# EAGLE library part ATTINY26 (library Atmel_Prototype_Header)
8-bit AVR Microcontroller with 2K Bytes Flash
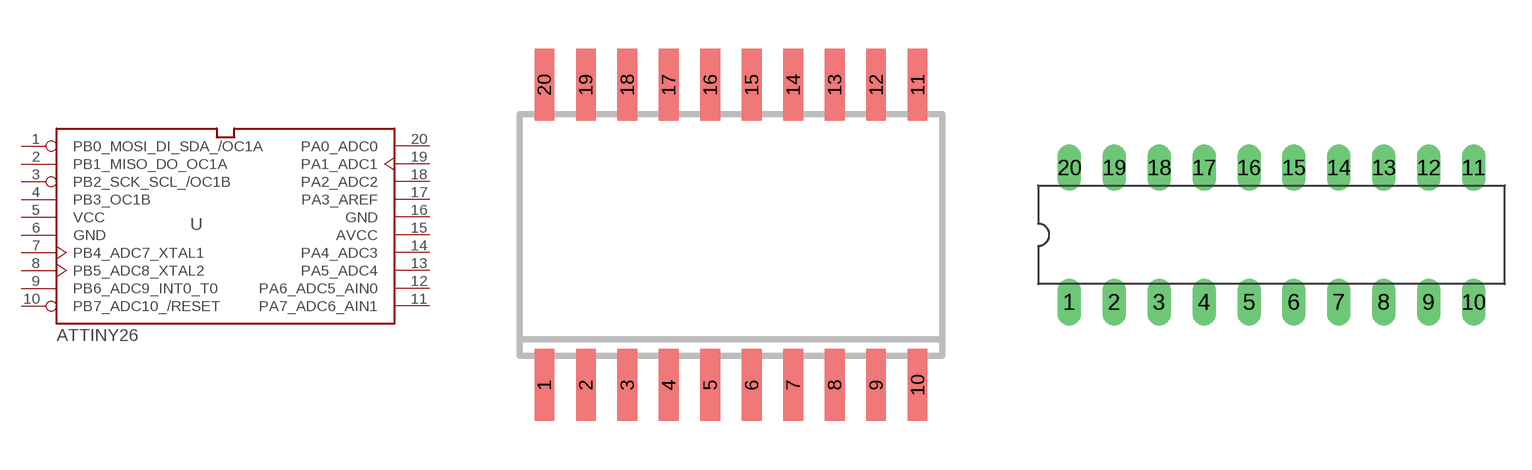
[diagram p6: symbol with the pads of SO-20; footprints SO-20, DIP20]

Designator prefix U

## ATTINY2616SI  [SO-20]
1  PB0_MOSI_DI_SDA_/OC1A  in
2  PB1_MISO_DO_OC1A  in
3  PB2_SCK_SCL_/OC1B  out
4  PB3_OC1B
5  VCC
6  GND
7  PB4_ADC7_XTAL1
8  PB5_ADC8_XTAL2
9  PB6_ADC9_INT0_T0
10  PB7_ADC10_/RESET  pwr
11  PA7_ADC6_AIN1
12  PA6_ADC5_AIN0
13  PA5_ADC4
14  PA4_ADC3
15  AVCC
16  GND
17  PA3_AREF
18  PA2_ADC2
19  PA1_ADC1
20  PA0_ADC0  pwr

## ATTINY2616PI  [DIP20]
Pads as for SO-20

## Footprint SO-20 (pad centres in mm)
smd 0.6 x 2.2: 1 -5.715,-4.6; 2 -4.445,-4.6; 3 -3.175,-4.6; 4 -1.905,-4.6; 5 -0.635,-4.6; 6 0.635,-4.6; 7 1.905,-4.6; 8 3.175,-4.6; 9 4.445,-4.6; 10 5.715,-4.6; 11 5.715,4.6; 12 4.445,4.6; 13 3.175,4.6; 14 1.905,4.6; 15 0.635,4.6; 16 -0.635,4.6; 17 -1.905,4.6; 18 -3.175,4.6; 19 -4.445,4.6; 20 -5.715,4.6

## Footprint DIP20 (pad centres in mm)
drill 0.813 long: 1 -11.43,-3.81; 2 -8.89,-3.81; 3 -6.35,-3.81; 4 -3.81,-3.81; 5 -1.27,-3.81; 6 1.27,-3.81; 7 3.81,-3.81; 8 6.35,-3.81; 9 8.89,-3.81; 10 11.43,-3.81; 11 11.43,3.81; 12 8.89,3.81; 13 6.35,3.81; 14 3.81,3.81; 15 1.27,3.81; 16 -1.27,3.81; 17 -3.81,3.81; 18 -6.35,3.81; 19 -8.89,3.81; 20 -11.43,3.81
